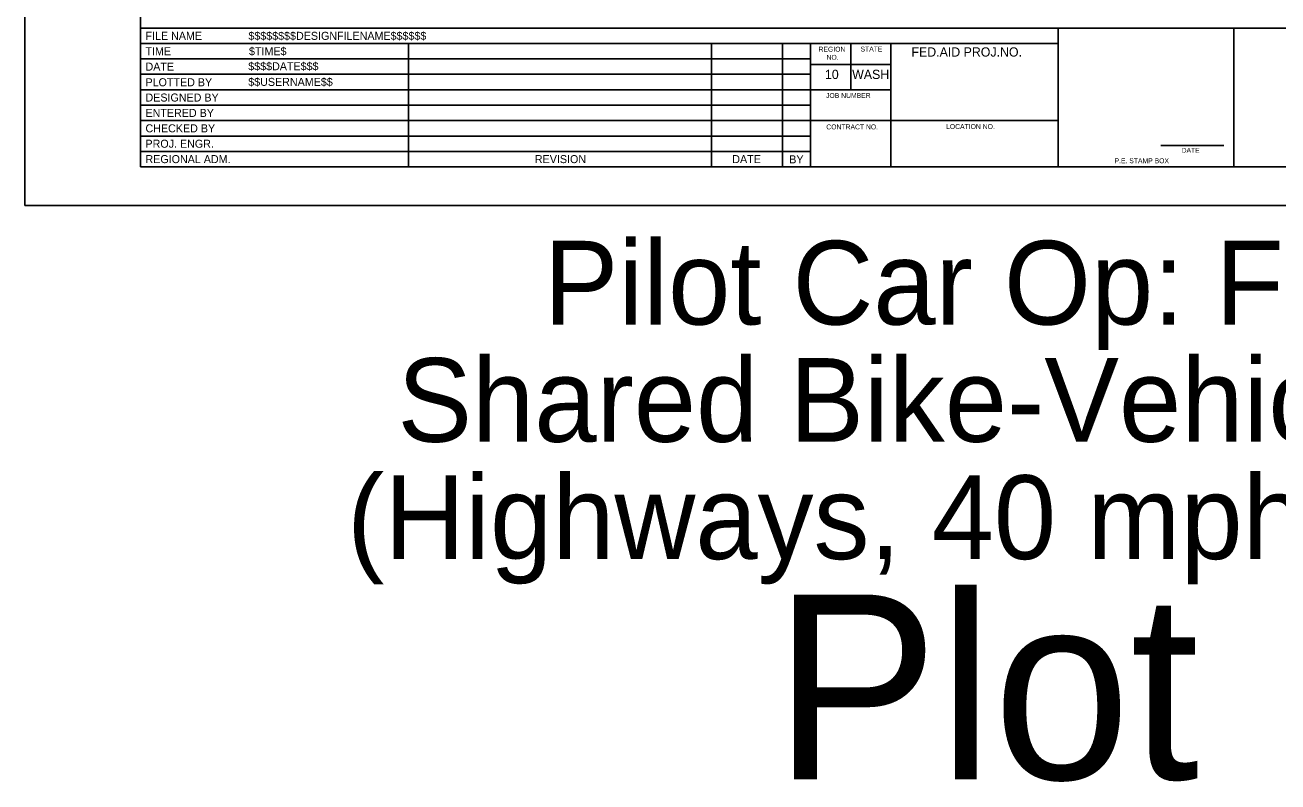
# Model space of a CAD drawing. Extents: x 99999.1 to 100095.7, y 99995 to 100010.7.
# Drawn here: x 99999.06 to 100009.24, y 99995.01 to 100001.15 of the extents above; entities that cross this region are included whole.
import ezdxf

# ---------------------------------------------------------------- set-up
doc = ezdxf.new("R2010")
doc.units = 0
for name, color, linetype in [('SH_GI_PlotLimits', 7, 'Continuous'), ('SH_GI_SheetBorder', 7, 'Continuous'), ('SH_GI_SheetLocationText', 7, 'Continuous'), ('SH_GI_SheetTextInCells', 7, 'Continuous'), ('SH_GI_TitleBlockText', 7, 'Continuous')]:
    doc.layers.add(name, color=color, linetype=linetype)

msp = doc.modelspace()

# ---------------------------------------------------------------- linework, layer by layer
at = {"layer": 'SH_GI_PlotLimits'}
msp.add_lwpolyline([(99999.062, 99999.687), (100016.062, 99999.687), (100016.062, 100010.687), (99999.062, 100010.687)], close=True, dxfattribs=at)
at = {"layer": 'SH_GI_SheetBorder'}
for p, q in [((100000, 100010.375), (100000, 100000)), ((100000, 100001.126), (100015.75, 100001.126)), ((100007.457, 100000), (100007.457, 100001.126)), ((100008.883, 100000), (100008.883, 100001.126)), ((100000, 100001.001), (100007.457, 100001.001)), ((100002.179, 100001.001), (100002.179, 100000)), ((100004.641, 100001.001), (100004.641, 100000)), ((100005.216, 100001.001), (100005.216, 100000)), ((100005.445, 100001.001), (100005.445, 100000)), ((100005.772, 100000.625), (100005.772, 100001.001)), ((100006.096, 100000), (100006.096, 100001.001)), ((100000, 100000.876), (100002.182, 100000.876)), ((100002.182, 100000.876), (100005.447, 100000.876)), ((100006.096, 100000.831), (100005.447, 100000.831)), ((100000, 100000.751), (100002.182, 100000.751)), ((100002.182, 100000.751), (100005.447, 100000.751)), ((100000, 100000.625), (100005.447, 100000.625)), ((100006.096, 100000.625), (100005.447, 100000.625)), ((100000, 100000.5), (100005.447, 100000.5)), ((100000, 100000.375), (100005.447, 100000.375)), ((100007.457, 100000.375), (100005.447, 100000.375)), ((100000, 100000.25), (100005.447, 100000.25)), ((100000, 100000.125), (100005.447, 100000.125)), ((100008.29, 100000.173), (100008.802, 100000.173)), ((100000, 100000), (100015.75, 100000))]:
    msp.add_line(p, q, dxfattribs=at)

# ---------------------------------------------------------------- texts
at = {"layer": 'SH_GI_SheetLocationText'}
for s, height, p in [('Pilot Car Op: Flagger', 0.68, (100003.277, 99998.719)), ('Shared Bike-Vehicle Lane', 0.68, (100002.088, 99997.767)), ('(Highways, 40 mph or Less)', 0.68, (100001.679, 99996.815)), ('Plot 1', 1.5, (100005.145, 99995.027))]:
    msp.add_text(s, height=height, dxfattribs=at).set_placement(p)
at = {"layer": 'SH_GI_SheetTextInCells'}
for s, height, p in [('FILE NAME', 0.0651, (100000.041, 100001.031)), ('TIME', 0.0651, (100000.041, 100000.906)), ('REGION', 0.04, (100005.51, 100000.935)), ('STATE', 0.04, (100005.851, 100000.936)), ('FED.AID PROJ.NO.', 0.07506, (100006.265, 100000.895)), ('DATE', 0.0651, (100000.041, 100000.781)), ('NO.', 0.04, (100005.575, 100000.869)), ('PLOTTED BY', 0.0651, (100000.041, 100000.654)), ('10', 0.0751, (100005.562, 100000.713)), ('WASH', 0.0751, (100005.783, 100000.713)), ('DESIGNED BY', 0.06505, (100000.041, 100000.53)), ('JOB NUMBER', 0.04, (100005.571, 100000.559)), ('ENTERED BY', 0.0651, (100000.041, 100000.405)), ('CHECKED BY', 0.0651, (100000.041, 100000.28)), ('CONTRACT NO.', 0.04003, (100005.573, 100000.304)), ('LOCATION NO.', 0.04003, (100006.546, 100000.307)), ('PROJ. ENGR.', 0.06505, (100000.041, 100000.155)), ('DATE', 0.04, (100008.46, 100000.114)), ('REGIONAL ADM.', 0.06505, (100000.041, 100000.03)), ('REVISION', 0.0651, (100003.205, 100000.03)), ('DATE', 0.0651, (100004.809, 100000.03)), ('BY', 0.0651, (100005.272, 100000.028)), ('P.E. STAMP BOX', 0.04003, (100007.915, 100000.029))]:
    msp.add_text(s, height=height, dxfattribs=at).set_placement(p)
at = {"layer": 'SH_GI_TitleBlockText'}
for s, height, p in [('$$$$$$$$DESIGNFILENAME$$$$$$', 0.06505, (100000.877, 100001.031)), ('$TIME$', 0.0651, (100000.882, 100000.906)), ('$$$$DATE$$$', 0.06505, (100000.876, 100000.784)), ('$$USERNAME$$', 0.06505, (100000.876, 100000.657))]:
    msp.add_text(s, height=height, dxfattribs=at).set_placement(p)

doc.saveas('drawing.dxf')
